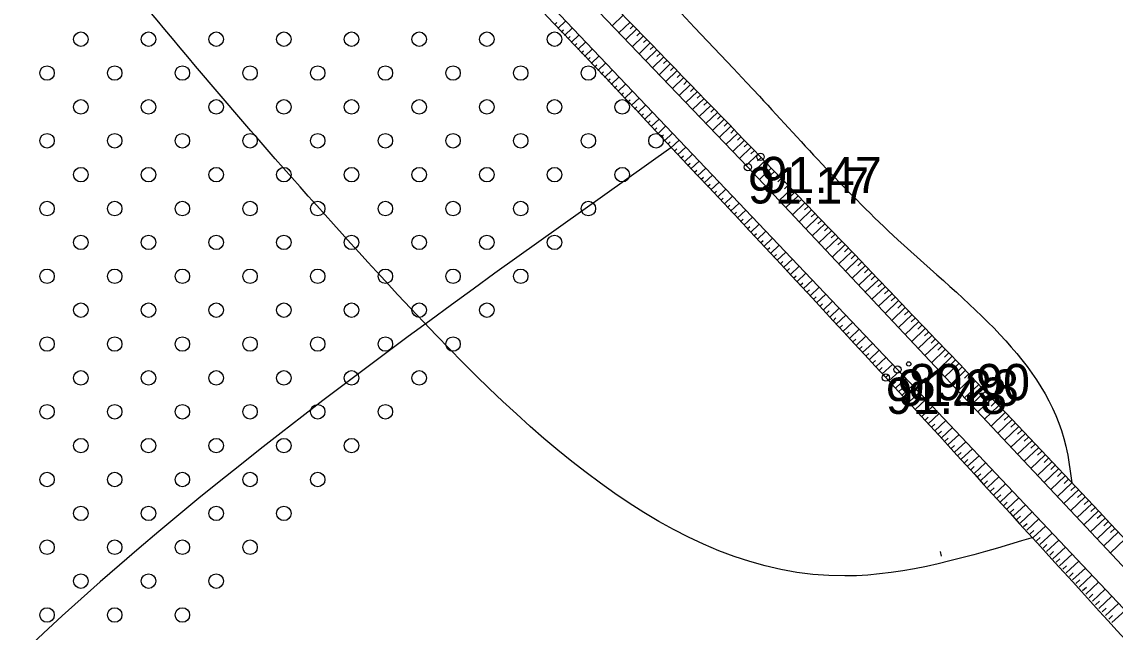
# Model space of a CAD drawing. Extents: x 316000 to 728450, y 314368 to 726000.
# Drawn here: x 726103.9 to 726217, y 315127.7 to 315190.8 of the extents above; entities that cross this region are included whole.
import ezdxf

# ---------------------------------------------------------------- set-up
doc = ezdxf.new("R2010")
doc.units = 0
for name, color, linetype in [('HIDG_ELEM_####_####_#', 7, 'Continuous'), ('HIDG_GRAV_####_####_#', 7, 'Continuous'), ('RELJ_AATZ_####_TKST_#', 7, 'Continuous'), ('RELJ_ELEM_####_####_#', 7, 'Continuous'), ('RELJ_HORZ_PAMT_####_#', 7, 'Continuous'), ('RELJ_NOGA_####_####_#', 7, 'Continuous'), ('TERT_ELEM_####_####_#', 7, 'Continuous'), ('TERT_KONT_####_####_#', 7, 'Continuous')]:
    doc.layers.add(name, color=color, linetype=linetype)

msp = doc.modelspace()

# ---------------------------------------------------------------- linework, layer by layer
at = {"layer": 'HIDG_ELEM_####_####_#'}
msp.add_circle((726195.64, 315155.44), 0.225, dxfattribs=at)
at = {"layer": 'HIDG_GRAV_####_####_#'}
for points in [[(726259.18, 315086.52), (726260.77, 315088.86), (726179.01, 315175.77), (726127.86, 315229.06), (726063.06, 315296.07), (725998.34, 315364.32), (725936.65, 315430.32), (725875.35, 315494.08), (725809.44, 315562.19), (725743.94, 315631.87)], [(725741.16, 315628.11), (725806.06, 315558.99), (725870.9, 315491.87), (725934.12, 315427.08), (725995.78, 315361.63), (726059.85, 315293.4), (726126.03, 315226.73), (726194.49, 315154.86), (726259.18, 315086.52)]]:
    msp.add_lwpolyline(points, dxfattribs=at)
at = {"layer": 'RELJ_ELEM_####_####_#'}
for centre in [(726180.31, 315176.84), (726179.01, 315175.77), (726193.27, 315154.03), (726194.49, 315154.86)]:
    msp.add_circle(centre, 0.375, dxfattribs=at)
at = {"layer": 'RELJ_HORZ_PAMT_####_#'}
msp.add_line((726198.9, 315136.06), (726199, 315135.57), dxfattribs=at)
for points in [[(726116.34, 315699.09), (726105.94, 315702.69), (726040.13, 315715), (725990.82, 315710.42), (725942.03, 315708.25), (725920.28, 315706.77), (725880.37, 315714.51), (725859.05, 315708.68), (725859.05, 315672.66), (725851.26, 315613.97), (725853.47, 315568.9), (725841, 315555.79), (725885.56, 315509.63), (725935.94, 315461.49), (725983.42, 315406.25), (726032.86, 315360.51), (726082.85, 315311.19), (726122.23, 315248.76), (726137.05, 315229.29), (726180.19, 315183.1), (726194.52, 315168.27), (726211.91, 315146.93), (726212.51, 315143.16)], [(726208.53, 315137.52), (726189.05, 315133.53), (726141.5, 315164), (726090.79, 315224.6)]]:
    msp.add_spline(points, degree=3, dxfattribs=at)
at = {"layer": 'RELJ_NOGA_####_####_#'}
for p, q in [((726159.01, 315190.47), (726159.25, 315190.71)), ((726159.35, 315190.11), (726160.17, 315190.89)), ((726166.11, 315191.49), (726164.98, 315190.38)), ((726166.81, 315190.77), (726165.67, 315189.66)), ((726159.7, 315189.75), (726159.94, 315189.98)), ((726160.04, 315189.39), (726160.86, 315190.17)), ((726160.73, 315188.66), (726161.55, 315189.44)), ((726167.51, 315190.06), (726166.36, 315188.94)), ((726167.16, 315190.42), (726166.82, 315190.08)), ((726168.21, 315189.34), (726167.05, 315188.22)), ((726167.86, 315189.7), (726167.51, 315189.36)), ((726160.39, 315189.03), (726160.63, 315189.26)), ((726161.08, 315188.3), (726161.32, 315188.54)), ((726161.42, 315187.94), (726162.24, 315188.72)), ((726168.9, 315188.62), (726167.75, 315187.5)), ((726168.55, 315188.98), (726168.21, 315188.64)), ((726169.25, 315188.26), (726168.9, 315187.93)), ((726161.76, 315187.58), (726162.01, 315187.81)), ((726162.11, 315187.22), (726162.93, 315187.99)), ((726162.45, 315186.85), (726162.7, 315187.09)), ((726162.8, 315186.49), (726163.62, 315187.27)), ((726169.6, 315187.91), (726168.44, 315186.78)), ((726170.3, 315187.19), (726169.13, 315186.05)), ((726169.95, 315187.55), (726169.6, 315187.21)), ((726163.14, 315186.13), (726163.39, 315186.36)), ((726163.49, 315185.77), (726164.31, 315186.55)), ((726170.99, 315186.47), (726169.82, 315185.33)), ((726170.65, 315186.83), (726170.29, 315186.49)), ((726171.34, 315186.11), (726170.99, 315185.77)), ((726163.83, 315185.4), (726164.08, 315185.64)), ((726164.18, 315185.04), (726165, 315185.82)), ((726164.52, 315184.68), (726164.77, 315184.91)), ((726164.86, 315184.32), (726165.69, 315185.1)), ((726171.69, 315185.75), (726170.51, 315184.61)), ((726172.39, 315185.04), (726171.21, 315183.89)), ((726172.04, 315185.39), (726171.69, 315185.05)), ((726165.21, 315183.95), (726165.46, 315184.19)), ((726165.55, 315183.59), (726166.38, 315184.37)), ((726166.24, 315182.86), (726167.07, 315183.65)), ((726173.08, 315184.32), (726171.9, 315183.17)), ((726172.73, 315184.68), (726172.38, 315184.33)), ((726173.43, 315183.96), (726173.07, 315183.61)), ((726165.9, 315183.23), (726166.14, 315183.46)), ((726166.59, 315182.5), (726166.83, 315182.74)), ((726166.93, 315182.14), (726167.76, 315182.92)), ((726173.78, 315183.6), (726172.59, 315182.45)), ((726174.47, 315182.88), (726173.28, 315181.73)), ((726174.13, 315183.24), (726173.77, 315182.89)), ((726174.82, 315182.52), (726174.46, 315182.18)), ((726167.27, 315181.78), (726167.52, 315182.01)), ((726167.62, 315181.41), (726168.45, 315182.2)), ((726168.3, 315180.69), (726169.14, 315181.48)), ((726175.17, 315182.16), (726173.97, 315181.01)), ((726175.86, 315181.44), (726174.67, 315180.29)), ((726175.52, 315181.8), (726175.16, 315181.46)), ((726167.96, 315181.05), (726168.21, 315181.29)), ((726168.65, 315180.32), (726168.9, 315180.56)), ((726168.99, 315179.96), (726169.83, 315180.75)), ((726176.56, 315180.72), (726175.36, 315179.57)), ((726176.21, 315181.08), (726175.85, 315180.74)), ((726176.91, 315180.37), (726176.55, 315180.02)), ((726169.34, 315179.6), (726169.59, 315179.83)), ((726169.68, 315179.23), (726170.52, 315180.03)), ((726170.37, 315178.51), (726171.21, 315179.3)), ((726177.25, 315180.01), (726176.05, 315178.84)), ((726177.95, 315179.29), (726176.74, 315178.12)), ((726177.6, 315179.65), (726177.24, 315179.3)), ((726170.02, 315178.87), (726170.27, 315179.11)), ((726170.71, 315178.14), (726170.96, 315178.38)), ((726171.05, 315177.78), (726171.9, 315178.58)), ((726178.64, 315178.57), (726177.44, 315177.4)), ((726178.3, 315178.93), (726177.93, 315178.58)), ((726178.99, 315178.21), (726178.63, 315177.86)), ((726171.4, 315177.42), (726171.65, 315177.66)), ((726171.74, 315177.05), (726172.59, 315177.85)), ((726172.08, 315176.69), (726172.34, 315176.93)), ((726172.43, 315176.33), (726173.28, 315177.13)), ((726179.34, 315177.85), (726178.13, 315176.68)), ((726180.03, 315177.13), (726178.82, 315175.96)), ((726179.68, 315177.49), (726179.32, 315177.14)), ((726172.77, 315175.96), (726173.02, 315176.2)), ((726173.11, 315175.6), (726173.97, 315176.41)), ((726180.72, 315176.4), (726179.51, 315175.23)), ((726180.38, 315176.77), (726180.01, 315176.42)), ((726181.07, 315176.04), (726180.7, 315175.69)), ((726173.45, 315175.24), (726173.71, 315175.48)), ((726173.8, 315174.87), (726174.66, 315175.68)), ((726174.14, 315174.51), (726174.4, 315174.75)), ((726174.48, 315174.14), (726175.35, 315174.96)), ((726181.42, 315175.68), (726180.19, 315174.51)), ((726182.11, 315174.96), (726180.88, 315173.78)), ((726181.76, 315175.32), (726181.39, 315174.97)), ((726182.46, 315174.6), (726182.09, 315174.25)), ((726174.83, 315173.78), (726175.09, 315174.02)), ((726175.17, 315173.42), (726176.04, 315174.23)), ((726175.85, 315172.69), (726176.73, 315173.51)), ((726182.8, 315174.24), (726181.56, 315173.05)), ((726183.5, 315173.52), (726182.25, 315172.32)), ((726183.15, 315173.88), (726182.78, 315173.52)), ((726175.51, 315173.05), (726175.77, 315173.3)), ((726176.2, 315172.32), (726176.46, 315172.57)), ((726176.54, 315171.96), (726177.42, 315172.78)), ((726184.19, 315172.8), (726182.93, 315171.59)), ((726183.84, 315173.16), (726183.47, 315172.8)), ((726184.54, 315172.44), (726184.16, 315172.08)), ((726176.88, 315171.59), (726177.15, 315171.84)), ((726177.22, 315171.23), (726178.11, 315172.06)), ((726177.91, 315170.5), (726178.8, 315171.34)), ((726184.88, 315172.08), (726183.62, 315170.86)), ((726185.58, 315171.36), (726184.3, 315170.14)), ((726185.23, 315171.72), (726184.85, 315171.35)), ((726177.57, 315170.87), (726177.83, 315171.12)), ((726178.25, 315170.14), (726178.52, 315170.39)), ((726178.59, 315169.77), (726179.49, 315170.61)), ((726186.27, 315170.64), (726184.99, 315169.41)), ((726185.92, 315171), (726185.54, 315170.63)), ((726186.61, 315170.28), (726186.23, 315169.91)), ((726178.94, 315169.41), (726179.2, 315169.66)), ((726179.28, 315169.04), (726180.18, 315169.89)), ((726179.96, 315168.31), (726180.87, 315169.16)), ((726186.96, 315169.92), (726185.67, 315168.68)), ((726187.65, 315169.2), (726186.36, 315167.95)), ((726187.31, 315169.56), (726186.92, 315169.18)), ((726179.62, 315168.68), (726179.89, 315168.93)), ((726180.3, 315167.95), (726180.58, 315168.2)), ((726180.65, 315167.58), (726181.56, 315168.44)), ((726188.35, 315168.47), (726187.04, 315167.22)), ((726188, 315168.83), (726187.61, 315168.46)), ((726188.69, 315168.11), (726188.3, 315167.74)), ((726180.99, 315167.22), (726181.26, 315167.48)), ((726181.33, 315166.85), (726182.25, 315167.71)), ((726181.67, 315166.49), (726181.95, 315166.75)), ((726182.01, 315166.12), (726182.94, 315166.99)), ((726189.04, 315167.75), (726187.73, 315166.49)), ((726189.73, 315167.03), (726188.41, 315165.77)), ((726189.38, 315167.39), (726188.99, 315167.01)), ((726182.35, 315165.76), (726182.63, 315166.02)), ((726182.7, 315165.39), (726183.63, 315166.26)), ((726190.42, 315166.31), (726189.1, 315165.04)), ((726190.08, 315166.67), (726189.68, 315166.29)), ((726191.12, 315165.59), (726189.78, 315164.31)), ((726190.77, 315165.95), (726190.37, 315165.57)), ((726183.04, 315165.03), (726183.32, 315165.29)), ((726183.38, 315164.66), (726184.32, 315165.54)), ((726183.72, 315164.3), (726184, 315164.56)), ((726184.06, 315163.93), (726185.01, 315164.82)), ((726191.81, 315164.87), (726190.47, 315163.58)), ((726191.46, 315165.23), (726191.06, 315164.84)), ((726192.15, 315164.51), (726191.75, 315164.12)), ((726184.4, 315163.57), (726184.69, 315163.83)), ((726184.74, 315163.2), (726185.7, 315164.09)), ((726185.43, 315162.47), (726186.39, 315163.37)), ((726192.5, 315164.14), (726191.15, 315162.85)), ((726193.19, 315163.42), (726191.84, 315162.13)), ((726192.85, 315163.78), (726192.44, 315163.4)), ((726185.08, 315162.84), (726185.37, 315163.1)), ((726185.77, 315162.1), (726186.06, 315162.37)), ((726186.11, 315161.74), (726187.08, 315162.64)), ((726193.88, 315162.7), (726192.52, 315161.4)), ((726193.54, 315163.06), (726193.13, 315162.67)), ((726194.23, 315162.34), (726193.82, 315161.95)), ((726186.45, 315161.37), (726186.74, 315161.64)), ((726186.79, 315161.01), (726187.77, 315161.92)), ((726187.47, 315160.27), (726188.46, 315161.19)), ((726194.58, 315161.98), (726193.21, 315160.67)), ((726195.27, 315161.26), (726193.89, 315159.94)), ((726194.92, 315161.62), (726194.51, 315161.22)), ((726187.13, 315160.64), (726187.42, 315160.92)), ((726187.81, 315159.91), (726188.11, 315160.19)), ((726188.15, 315159.54), (726189.15, 315160.47)), ((726195.96, 315160.53), (726194.58, 315159.21)), ((726195.61, 315160.9), (726195.2, 315160.5)), ((726196.3, 315160.17), (726195.89, 315159.78)), ((726188.49, 315159.18), (726188.79, 315159.46)), ((726188.83, 315158.81), (726189.84, 315159.74)), ((726189.51, 315158.08), (726190.53, 315159.02)), ((726196.65, 315159.81), (726195.26, 315158.48)), ((726197.34, 315159.09), (726195.95, 315157.76)), ((726197, 315159.45), (726196.58, 315159.05)), ((726189.17, 315158.44), (726189.48, 315158.73)), ((726189.85, 315157.71), (726190.16, 315158)), ((726190.19, 315157.34), (726191.22, 315158.3)), ((726198.03, 315158.37), (726196.63, 315157.03)), ((726197.69, 315158.73), (726197.27, 315158.33)), ((726198.72, 315157.64), (726197.32, 315156.3)), ((726198.38, 315158), (726197.96, 315157.6)), ((726190.53, 315156.98), (726190.84, 315157.26)), ((726190.87, 315156.61), (726191.91, 315157.57)), ((726191.21, 315156.24), (726191.53, 315156.53)), ((726191.55, 315155.88), (726192.6, 315156.85)), ((726199.41, 315156.92), (726198, 315155.57)), ((726199.07, 315157.28), (726198.65, 315156.88)), ((726199.76, 315156.56), (726199.34, 315156.15)), ((726191.89, 315155.51), (726192.21, 315155.8)), ((726192.23, 315155.14), (726193.29, 315156.12)), ((726192.91, 315154.41), (726193.98, 315155.4)), ((726200.11, 315156.2), (726198.69, 315154.84)), ((726200.8, 315155.47), (726199.37, 315154.12)), ((726200.45, 315155.84), (726200.02, 315155.43)), ((726192.57, 315154.78), (726192.89, 315155.07)), ((726193.25, 315154.04), (726193.57, 315154.34)), ((726193.59, 315153.68), (726194.67, 315154.67)), ((726201.49, 315154.75), (726200.06, 315153.39)), ((726201.14, 315155.11), (726200.71, 315154.7)), ((726201.83, 315154.39), (726201.4, 315153.98)), ((726193.93, 315153.31), (726194.26, 315153.61)), ((726194.27, 315152.94), (726195.36, 315153.95)), ((726194.95, 315152.21), (726196.04, 315153.22)), ((726202.18, 315154.03), (726200.74, 315152.66)), ((726202.87, 315153.3), (726201.43, 315151.93)), ((726202.52, 315153.67), (726202.09, 315153.25)), ((726194.61, 315152.58), (726194.94, 315152.88)), ((726195.29, 315151.84), (726195.62, 315152.15)), ((726195.63, 315151.47), (726196.73, 315152.49)), ((726203.56, 315152.58), (726202.11, 315151.2)), ((726203.21, 315152.94), (726202.78, 315152.53)), ((726203.9, 315152.22), (726203.47, 315151.8)), ((726195.97, 315151.11), (726196.3, 315151.41)), ((726196.31, 315150.74), (726197.42, 315151.77)), ((726196.99, 315150.01), (726198.11, 315151.04)), ((726204.25, 315151.86), (726202.8, 315150.48)), ((726204.94, 315151.13), (726203.48, 315149.75)), ((726204.59, 315151.49), (726204.16, 315151.08)), ((726196.65, 315150.37), (726196.98, 315150.68)), ((726197.33, 315149.64), (726197.66, 315149.95)), ((726197.67, 315149.27), (726198.79, 315150.31)), ((726205.63, 315150.41), (726204.17, 315149.02)), ((726205.28, 315150.77), (726204.84, 315150.35)), ((726205.97, 315150.05), (726205.53, 315149.63)), ((726198, 315148.9), (726198.34, 315149.22)), ((726198.34, 315148.54), (726199.48, 315149.59)), ((726199.02, 315147.8), (726200.17, 315148.86)), ((726206.32, 315149.68), (726204.85, 315148.29)), ((726207, 315148.96), (726205.54, 315147.56)), ((726206.66, 315149.32), (726206.22, 315148.9)), ((726207.35, 315148.6), (726206.91, 315148.18)), ((726198.68, 315148.17), (726199.03, 315148.49)), ((726199.36, 315147.44), (726199.71, 315147.76)), ((726199.7, 315147.07), (726200.86, 315148.14)), ((726207.69, 315148.23), (726206.22, 315146.84)), ((726208.38, 315147.51), (726206.91, 315146.11)), ((726208.04, 315147.87), (726207.6, 315147.45)), ((726200.04, 315146.7), (726200.39, 315147.02)), ((726200.38, 315146.34), (726201.54, 315147.41)), ((726201.06, 315145.6), (726202.23, 315146.68)), ((726209.07, 315146.78), (726207.59, 315145.38)), ((726208.73, 315147.15), (726208.28, 315146.73)), ((726209.42, 315146.42), (726208.97, 315146)), ((726200.72, 315145.97), (726201.07, 315146.29)), ((726201.4, 315145.23), (726201.75, 315145.56)), ((726201.74, 315144.87), (726202.92, 315145.96)), ((726202.42, 315144.13), (726203.6, 315145.23)), ((726209.76, 315146.06), (726208.28, 315144.65)), ((726210.45, 315145.33), (726208.96, 315143.92)), ((726210.1, 315145.7), (726209.66, 315145.27)), ((726202.08, 315144.5), (726202.43, 315144.83)), ((726202.76, 315143.77), (726203.11, 315144.1)), ((726203.1, 315143.4), (726204.29, 315144.5)), ((726211.14, 315144.61), (726209.65, 315143.2)), ((726210.79, 315144.97), (726210.35, 315144.55)), ((726211.48, 315144.25), (726211.03, 315143.82)), ((726203.44, 315143.03), (726203.8, 315143.36)), ((726203.78, 315142.66), (726204.98, 315143.78)), ((726204.45, 315141.93), (726205.67, 315143.05)), ((726211.82, 315143.88), (726210.33, 315142.47)), ((726212.51, 315143.16), (726211.02, 315141.74)), ((726212.17, 315143.52), (726211.72, 315143.09)), ((726204.12, 315142.3), (726204.48, 315142.63)), ((726204.79, 315141.56), (726205.16, 315141.9)), ((726205.13, 315141.2), (726206.35, 315142.32)), ((726213.2, 315142.43), (726211.7, 315141.01)), ((726212.86, 315142.79), (726212.41, 315142.37)), ((726213.54, 315142.07), (726213.09, 315141.64)), ((726205.47, 315140.83), (726205.84, 315141.17)), ((726205.81, 315140.46), (726207.04, 315141.6)), ((726206.49, 315139.73), (726207.73, 315140.87)), ((726213.89, 315141.7), (726212.39, 315140.28)), ((726214.57, 315140.98), (726213.07, 315139.56)), ((726214.23, 315141.34), (726213.78, 315140.91)), ((726206.15, 315140.09), (726206.52, 315140.44)), ((726206.83, 315139.36), (726207.2, 315139.7)), ((726207.17, 315138.99), (726208.42, 315140.15)), ((726215.26, 315140.25), (726213.76, 315138.83)), ((726214.92, 315140.61), (726214.47, 315140.19)), ((726215.61, 315139.89), (726215.15, 315139.46)), ((726207.51, 315138.63), (726207.89, 315138.97)), ((726207.85, 315138.26), (726209.1, 315139.42)), ((726208.53, 315137.52), (726209.79, 315138.69)), ((726215.95, 315139.52), (726214.44, 315138.1)), ((726216.64, 315138.8), (726215.13, 315137.37)), ((726216.29, 315139.16), (726215.84, 315138.73)), ((726216.98, 315138.43), (726216.53, 315138.01)), ((726208.19, 315137.89), (726208.57, 315138.24)), ((726208.87, 315137.16), (726209.25, 315137.51)), ((726209.21, 315136.79), (726210.48, 315137.97)), ((726217.32, 315138.07), (726215.81, 315136.64)), ((726218.01, 315137.34), (726216.5, 315135.92)), ((726209.55, 315136.42), (726209.93, 315136.78)), ((726209.89, 315136.06), (726211.17, 315137.24)), ((726210.56, 315135.32), (726211.85, 315136.51)), ((726210.23, 315135.69), (726210.61, 315136.05)), ((726210.9, 315134.95), (726211.29, 315135.31)), ((726211.24, 315134.59), (726212.54, 315135.79)), ((726211.92, 315133.85), (726213.23, 315135.06)), ((726211.58, 315134.22), (726211.97, 315134.58)), ((726212.6, 315133.12), (726213.92, 315134.34)), ((726212.26, 315133.49), (726212.66, 315133.85)), ((726212.94, 315132.75), (726213.34, 315133.12)), ((726213.28, 315132.39), (726214.6, 315133.61)), ((726213.96, 315131.65), (726215.29, 315132.88)), ((726213.62, 315132.02), (726214.02, 315132.39)), ((726214.3, 315131.28), (726214.7, 315131.65)), ((726214.64, 315130.92), (726215.98, 315132.16)), ((726214.98, 315130.55), (726215.38, 315130.92)), ((726215.32, 315130.18), (726216.67, 315131.43)), ((726216, 315129.45), (726217.35, 315130.7)), ((726215.66, 315129.82), (726216.06, 315130.19)), ((726216.34, 315129.08), (726216.74, 315129.46)), ((726216.67, 315128.71), (726218.04, 315129.98))]:
    msp.add_line(p, q, dxfattribs=at)
for points in [[(726259.12, 315084.51), (726262.72, 315089.26), (726261.56, 315090.84), (726260.2, 315092.42), (726257.29, 315095.53), (726218.91, 315136.38), (726180.31, 315176.84), (726128.67, 315229.97), (726063.7, 315298.11), (725999.9, 315366.09), (725937.21, 315432.09), (725876.35, 315495.23), (725810.58, 315563.08), (725744.7, 315632.91)], [(725740.86, 315626.98), (725805.54, 315558.12), (725870.39, 315491.15), (725932.8, 315426.8), (725994.98, 315360.84), (726059.66, 315292.12), (726075.75, 315275.46), (726092.08, 315259.04), (726108.47, 315242.67), (726124.69, 315226.14), (726193.27, 315154.03), (726250.06, 315092.6), (726256.32, 315085.83), (726258.82, 315084.29), (726259.12, 315084.51)]]:
    msp.add_spline(points, degree=3, dxfattribs=at)
at = {"layer": 'TERT_ELEM_####_####_#'}
for centre in [(726110, 315189), (726117, 315189), (726124, 315189), (726131, 315189), (726138, 315189), (726145, 315189), (726152, 315189), (726159, 315189), (726106.5, 315185.5), (726113.5, 315185.5), (726120.5, 315185.5), (726127.5, 315185.5), (726134.5, 315185.5), (726141.5, 315185.5), (726148.5, 315185.5), (726155.5, 315185.5), (726162.5, 315185.5), (726110, 315182), (726117, 315182), (726124, 315182), (726131, 315182), (726138, 315182), (726145, 315182), (726152, 315182), (726159, 315182), (726166, 315182), (726106.5, 315178.5), (726113.5, 315178.5), (726120.5, 315178.5), (726127.5, 315178.5), (726134.5, 315178.5), (726141.5, 315178.5), (726148.5, 315178.5), (726155.5, 315178.5), (726162.5, 315178.5), (726169.5, 315178.5), (726110, 315175), (726117, 315175), (726124, 315175), (726131, 315175), (726138, 315175), (726145, 315175), (726152, 315175), (726159, 315175), (726166, 315175), (726106.5, 315171.5), (726113.5, 315171.5), (726120.5, 315171.5), (726127.5, 315171.5), (726134.5, 315171.5), (726141.5, 315171.5), (726148.5, 315171.5), (726155.5, 315171.5), (726162.5, 315171.5), (726110, 315168), (726117, 315168), (726124, 315168), (726131, 315168), (726138, 315168), (726145, 315168), (726152, 315168), (726159, 315168), (726106.5, 315164.5), (726113.5, 315164.5), (726120.5, 315164.5), (726127.5, 315164.5), (726134.5, 315164.5), (726141.5, 315164.5), (726148.5, 315164.5), (726155.5, 315164.5), (726110, 315161), (726117, 315161), (726124, 315161), (726131, 315161), (726138, 315161), (726145, 315161), (726152, 315161), (726106.5, 315157.5), (726113.5, 315157.5), (726120.5, 315157.5), (726127.5, 315157.5), (726134.5, 315157.5), (726141.5, 315157.5), (726148.5, 315157.5), (726110, 315154), (726117, 315154), (726124, 315154), (726131, 315154), (726138, 315154), (726145, 315154), (726106.5, 315150.5), (726113.5, 315150.5), (726120.5, 315150.5), (726127.5, 315150.5), (726134.5, 315150.5), (726141.5, 315150.5), (726110, 315147), (726117, 315147), (726124, 315147), (726131, 315147), (726138, 315147), (726106.5, 315143.5), (726113.5, 315143.5), (726120.5, 315143.5), (726127.5, 315143.5), (726134.5, 315143.5), (726110, 315140), (726117, 315140), (726124, 315140), (726131, 315140), (726106.5, 315136.5), (726113.5, 315136.5), (726120.5, 315136.5), (726127.5, 315136.5), (726110, 315133), (726117, 315133), (726124, 315133), (726106.5, 315129.5), (726113.5, 315129.5), (726120.5, 315129.5)]:
    msp.add_circle(centre, 0.75, dxfattribs=at)
at = {"layer": 'TERT_KONT_####_####_#'}
msp.add_spline([(726171.05, 315177.78), (726060.22, 315058.34), (726046.85, 314926.57), (725966, 314840.49), (725918.95, 314808.85), (725841.04, 314808.85), (725695.46, 314898.17)], degree=3, dxfattribs=at)

# ---------------------------------------------------------------- texts
at = {"layer": 'RELJ_AATZ_####_TKST_#'}
for s, p in [('91.47', (726180.31, 315173.09)), ('91.17', (726179.01, 315172.02)), ('89.90', (726195.64, 315151.69)), ('91.28', (726194.49, 315151.11)), ('91.48', (726193.27, 315150.28))]:
    msp.add_text(s, height=3.75, dxfattribs=at).set_placement(p)

doc.saveas('drawing.dxf')
